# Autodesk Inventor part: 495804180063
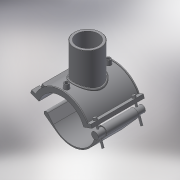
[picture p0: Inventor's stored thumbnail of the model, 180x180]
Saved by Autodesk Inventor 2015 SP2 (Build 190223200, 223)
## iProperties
Created: 2017-07
Part Number: 495804180063
Material: Generic
Description: PLASSON BRANCH SADDLE 180-63
Document SubType Name: Modeling
Designer: KIM
Density: 1 g/cm^3
Appearance: Default
Author: KIM
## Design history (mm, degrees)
derived "495804.ipt"
feature "Solid1::495804.ipt"
feature "Solid2::495804.ipt"
tag "TaggingFeature1"
body "Solid1"
body "Solid2"
other parameters: "d2" = 219, "d3" = 45, "d4" = 118, "d5" = 0, "d6" = 0.1, "d8" = 0, "d19" = 6, "d20" = 6, "d21" = 70.8, "d23" = 0, "d24" = 35.4, "d26" = 0, "d27" = 3, "d28" = 3, "d29" = 3, "d31" = 6, "d32" = 0, "d33" = 0, "d34" = 0.6, "d40" = 102.96, "d41" = 69.3, "d43" = 0, "d45" = 0, "d47" = 193, "d48" = 63, "d50" = 0, "d70" = 15, "d72" = 0, "d73" = 6, "d75" = 5, "d76" = 0, "d77" = 9, "d79" = 15, "d80" = 47.2, "d82" = 5 deg, "d84" = 4, "d85" = 14, "d86" = 0, "d87" = 3, "d88" = 0, "d89" = 1, "d90" = 1, "d91" = 94.4, "d92" = 0, "d93" = 0.5, "d94" = 94.73684, "d96" = 201.96, "d97" = 2.36, "d98" = 0, "d102" = 1.89, "d103" = 50.4, "d105" = 0, "d109" = -31.33333, "d117" = 0.63, "d120" = 140 deg, "d121" = 24.228, "d122" = 20 deg, "d123" = 396, "d124" = 118.8, "d126" = 0, "d143" = 189, "d150" = 32.4, "d159" = 3.6, "d161" = 4.5, "d162" = 70.8, "d163" = 0, "d167" = 36, "d173" = 1, "d176" = 20 deg, "d177" = 12.6, "d178" = 18, "d180" = 0, "d185" = 38.35, "d186" = 38.35, "d187" = 99, "d188" = 5.4, "d189" = 12.6, "d190" = 0, "d191" = 148.5, "d200" = 9, "d202" = 0, "d216" = 106.2, "d217" = 0, "d221" = 43.66, "d222" = 12.6, "d223" = 7.56, "d225" = 7.56, "d227" = 25.92, "d230" = 111.6, "d236" = 20 deg, "d237" = 106, "d238" = 20 deg, "d239" = 12.6, "B_" = 219, "H_" = 94, "L_" = 118, "d_t" = 6, "d_1" = 63, "H_1" = 85, "d1" = 198, "d148" = 4.5, "d160" = 4.5
